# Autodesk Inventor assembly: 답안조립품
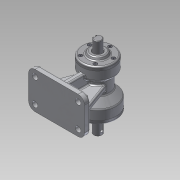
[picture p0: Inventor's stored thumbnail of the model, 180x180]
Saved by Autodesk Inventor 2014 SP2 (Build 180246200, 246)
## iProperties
Created: 2015-08
Part Number: 답안조립품
Document SubType Name: Assembly
Designer: 201-19
Author: 201-19
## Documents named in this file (10)
- C:\Users\201-19\Desktop\450805V1044\답안조립품.iam
- C:\Users\201-19\Desktop\450805V1044\본체.ipt
- C:\Users\201-19\Desktop\450805V1044\베어링 6205.ipt
- C:\Users\201-19\Desktop\450805V1044\베어링 6203.ipt
- C:\Users\201-19\Desktop\450805V1044\축.ipt
- C:\Users\201-19\Desktop\450805V1044\뒤커버.ipt
- C:\Users\201-19\Desktop\450805V1044\앞커버.ipt
- C:\Users\201-19\Desktop\450805V1044\오일실 .ipt
- 오일실 .ipt
- C:\Users\201-19\Desktop\450805V1044\M4x0.5.ipt
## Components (10 placed, 1 different names)
1. M4x0.5:1
2. M4x0.5:2
3. M4x0.5:3
4. M4x0.5:4
5. M4x0.5:5
6. M4x0.5:6
7. M4x0.5:7
8. M4x0.5:8
9. M4x0.5:9
10. M4x0.5:10
